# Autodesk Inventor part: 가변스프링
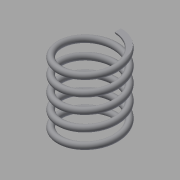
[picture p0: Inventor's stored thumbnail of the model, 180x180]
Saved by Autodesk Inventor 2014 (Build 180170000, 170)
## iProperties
Created: 2018-12
Part Number: 가변스프링
Material: Generic
Document SubType Name: Modeling
Designer: kh
Density: 1 g/cm^3
Appearance: Default
Mass: 0.872329 g
Surface Area: 17.726 cm^2
Volume: 0.872329 cm^3
Author: kh
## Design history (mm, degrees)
sketch "Sketch1"
  geometry: L1 (0, 0)-(9, 0); L2 (9, 0)-(9, 24.5); L3 (9, 24.5)-(0, 24.5); L4 (0, 24.5)-(0, 0); C1 r 1 at (9, 0)
  constraints: 8 end point, 2 parallel, 1 centre point, 1 coincident, 1 horizontal, 1 perpendicular
  dimensions: "d0" = 2 diameter of C1; "d1" = 18 diameter of L2 L4; "d2" = 24.5 distance of L1.end L2.end (derived)
coil "Coil1" sketch "Sketch1" pitch "d3" = 10; turns "d5" = 5; dims "d4" = 24.5 (= d2), "d6" = 0, angle "d7" = 90 deg, angle "d8" = 90 deg, "d9" = 0, "d10" = 0
workplane "Work Plane1"
workplane "Work Plane2"
split "Split1"
split "Split2"
body "Solid1"
other parameters: "d11" = 0, "d12" = 24.5 (= d2)
